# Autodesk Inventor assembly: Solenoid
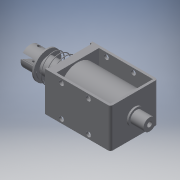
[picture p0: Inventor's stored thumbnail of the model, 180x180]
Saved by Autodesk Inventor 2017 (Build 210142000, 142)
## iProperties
Created: 2017-01
Part Number: Solenoid
Document SubType Name: Assembly
Designer: yul067
Author: yul067
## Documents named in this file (5)
- C:\Users\Mike\Desktop\Solenoid 1240S\Solenoid.iam
- C:\Users\Mike\Desktop\Solenoid 1240S\body.ipt
- C:\Users\Mike\Desktop\Solenoid 1240S\cylinder.ipt
- C:\Users\Mike\Desktop\Solenoid 1240S\shaft.ipt
- C:\Users\Mike\Desktop\Solenoid 1240S\spring.ipt
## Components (4 placed, 4 different names)
1. shaft:1 — Cylindrical:1
2. body:1 — Rigid:1, Cylindrical:1, Mate:1
3. cylinder:1 — Rigid:1
4. Spring:1 — Mate:1
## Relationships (3: WeldJoint 1, CylindricalJoint 1, Mate 1)
- Rigid:1 [WeldJoint]: body:1 ↔ cylinder:1
- Cylindrical:1: shaft:1 ↔ body:1
- Mate:1: body:1 ↔ Spring:1
